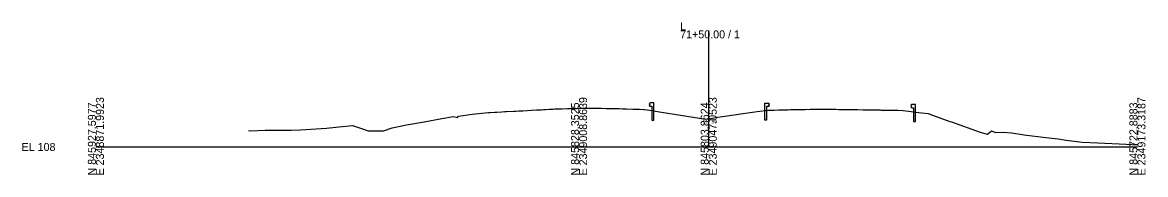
# Model space of a CAD drawing. Extents: x -26 to 2348767, y -10 to 845205.
# Drawn here: x 2164.2 to 2557.2, y 6990.3 to 7043.7 of the extents above; entities that cross this region are included whole.
import ezdxf

# ---------------------------------------------------------------- set-up
doc = ezdxf.new("R2010")
doc.units = 0
for name, color, linetype in [('Exist Cross Section Cell', 7, 'Continuous'), ('Exist XS Center Line Elevation Label', 7, 'Continuous'), ('Exist XS Ground Line', 7, 'Continuous'), ('Prop CMT Guardrail Graphics', 7, 'Continuous')]:
    doc.layers.add(name, color=color, linetype=linetype)

msp = doc.modelspace()

# ---------------------------------------------------------------- linework, layer by layer
at = {"layer": 'Exist Cross Section Cell'}
for p, q in [((2404.36, 7000), (2404.36, 7040.89)), ((2189.93, 7000), (2358.99, 7000)), ((2358.99, 7000), (2404.36, 7000)), ((2404.36, 7000), (2554.36, 7000))]:
    msp.add_line(p, q, dxfattribs=at)
at = {"layer": 'Exist XS Ground Line'}
msp.add_lwpolyline([(2243.28, 7005.72), (2243.91, 7005.61), (2249.21, 7005.85), (2253.63, 7005.9), (2258.23, 7005.89), (2261.56, 7005.99), (2270.67, 7006.55), (2273.91, 7006.9), (2279.71, 7007.52), (2282.91, 7006.46), (2285.23, 7005.63), (2286.9, 7005.67), (2290.53, 7005.68), (2293.54, 7006.75), (2298.62, 7007.8), (2304.74, 7008.85), (2310.97, 7010.01), (2315.06, 7010.66), (2316.46, 7010.35), (2316.79, 7010.8), (2321.61, 7011.51), (2327.33, 7012.04), (2327.87, 7012.04), (2329.49, 7012.16), (2330.18, 7012.21), (2332.01, 7012.33), (2332.97, 7012.38), (2333.64, 7012.41), (2336.16, 7012.54), (2336.89, 7012.58), (2337.93, 7012.64), (2338.72, 7012.69), (2339.27, 7012.72), (2342.33, 7012.88), (2344.08, 7012.98), (2345.44, 7013.05), (2345.87, 7013.08), (2346.49, 7013.12), (2347.19, 7013.16), (2348.54, 7013.25), (2349.79, 7013.31), (2350.34, 7013.34), (2351.11, 7013.37), (2351.55, 7013.38), (2353.02, 7013.41), (2355, 7013.46), (2357.8, 7013.53), (2358.38, 7013.54), (2359.27, 7013.56), (2360.25, 7013.58), (2360.84, 7013.6), (2361.43, 7013.61), (2362.48, 7013.63), (2363.94, 7013.61), (2366.73, 7013.56), (2368.51, 7013.53), (2369.72, 7013.51), (2371.05, 7013.48), (2372.69, 7013.45), (2372.99, 7013.44), (2374.22, 7013.4), (2375.61, 7013.35), (2377.81, 7013.29), (2378.28, 7013.27), (2378.59, 7013.26), (2380.12, 7013.2), (2381.61, 7013.12), (2381.92, 7013.1), (2382.81, 7013.06), (2383.64, 7012.94), (2387.89, 7012.23), (2403.34, 7009.71), (2404.36, 7009.9), (2407.58, 7010.48), (2421.34, 7012.45), (2425.12, 7012.86), (2425.72, 7012.89), (2426.76, 7012.93), (2427.2, 7012.95), (2428.8, 7012.99), (2429.12, 7013), (2429.71, 7013.02), (2432.13, 7013.08), (2432.97, 7013.09), (2434.39, 7013.12), (2435.06, 7013.14), (2436.21, 7013.16), (2438.07, 7013.18), (2439.85, 7013.21), (2441.02, 7013.22), (2441.66, 7013.22), (2442.67, 7013.23), (2443.99, 7013.23), (2445.2, 7013.22), (2446.74, 7013.2), (2447.3, 7013.22), (2448.87, 7013.2), (2449.89, 7013.19), (2450.69, 7013.18), (2451.87, 7013.17), (2452.88, 7013.16), (2454.3, 7013.14), (2455.88, 7013.11), (2456.55, 7013.1), (2458.45, 7013.05), (2458.77, 7013.05), (2459.71, 7013.06), (2461.15, 7013.03), (2461.77, 7013.02), (2463.06, 7012.99), (2464.3, 7012.97), (2464.72, 7012.96), (2465.81, 7012.95), (2467.7, 7012.91), (2470.6, 7012.86), (2472.37, 7012.8), (2478.78, 7011.98), (2481.19, 7011.68), (2482.66, 7011.11), (2488.75, 7008.96), (2489.31, 7008.76), (2499, 7005.26), (2499.7, 7005.1), (2501.92, 7004.51), (2503.35, 7005.7), (2504.71, 7005.08), (2507.21, 7005.18), (2510.47, 7005.01), (2514.77, 7004.28), (2522.3, 7003.26), (2526.65, 7002.84), (2529.37, 7002.34), (2535.04, 7001.73), (2540.54, 7001.49), (2550.41, 7000.93), (2554.36, 7000.78)], dxfattribs=at)
at = {"layer": 'Prop CMT Guardrail Graphics'}
for p, q in [((2383.81, 7015.45), (2383.54, 7015.16)), ((2383.54, 7015.16), (2383.81, 7014.87)), ((2383.81, 7014.87), (2383.54, 7014.58)), ((2383.54, 7014.58), (2383.81, 7014.29)), ((2385.14, 7015.45), (2383.81, 7015.45)), ((2385.14, 7009.45), (2385.14, 7015.45)), ((2423.96, 7009.41), (2423.96, 7015.41)), ((2423.96, 7015.41), (2425.3, 7015.41)), ((2425.3, 7015.41), (2425.57, 7015.12)), ((2425.57, 7015.12), (2425.3, 7014.83)), ((2425.3, 7014.83), (2425.57, 7014.54)), ((2425.57, 7014.54), (2425.3, 7014.24)), ((2475.37, 7014.95), (2475.1, 7014.66)), ((2475.1, 7014.66), (2475.37, 7014.37)), ((2476.7, 7014.95), (2475.37, 7014.95)), ((2476.7, 7008.95), (2476.7, 7014.95)), ((2383.81, 7014.29), (2384.48, 7014.29)), ((2384.48, 7014.29), (2384.48, 7009.45)), ((2425.3, 7014.24), (2424.63, 7014.24)), ((2424.63, 7014.24), (2424.63, 7009.41)), ((2475.37, 7014.37), (2475.1, 7014.08)), ((2475.1, 7014.08), (2475.37, 7013.78)), ((2475.37, 7013.78), (2476.04, 7013.78)), ((2476.04, 7013.78), (2476.04, 7008.95)), ((2384.48, 7009.45), (2385.14, 7009.45)), ((2424.63, 7009.41), (2423.96, 7009.41)), ((2476.04, 7008.95), (2476.7, 7008.95))]:
    msp.add_line(p, q, dxfattribs=at)

# ---------------------------------------------------------------- texts
at = {"layer": 'Exist Cross Section Cell'}
for s, p in [('L', (2394.36, 7040.89)), ('71+50.00 / 1', (2394.36, 7038.09)), ('EL 108', (2163.93, 6998.6))]:
    msp.add_text(s, height=2.8, dxfattribs=at).set_placement(p)
for s, p in [('N 845927.5977', (2189.93, 6990)), ('E 2348871.9923', (2192.73, 6990)), ('N 845828.3525', (2358.99, 6990)), ('E 2349008.8639', (2361.79, 6990)), ('N 845803.8624', (2404.36, 6990)), ('E 2349047.0523', (2407.16, 6990)), ('N 845722.8883', (2554.36, 6990)), ('E 2349173.3187', (2557.16, 6990))]:
    msp.add_text(s, height=2.8, rotation=90, dxfattribs=at).set_placement(p)
at = {"layer": 'Exist XS Center Line Elevation Label'}
msp.add_text('117.90', height=1.2, dxfattribs=at).set_placement((2402.2, 7008.3))

doc.saveas('drawing.dxf')
